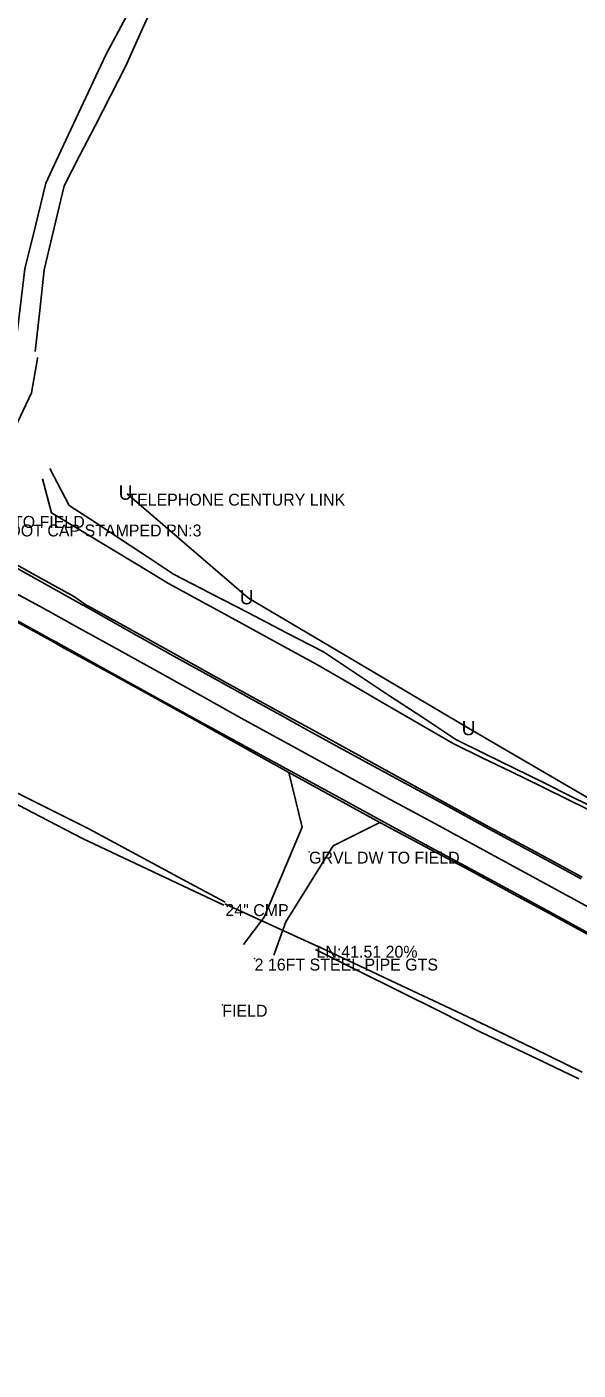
# Model space of a CAD drawing. Extents: x 1411444 to 1458157, y 300965 to 327300.
# Drawn here: x 1455057 to 1455288, y 302301 to 302865 of the extents above; entities that cross this region are included whole.
import ezdxf

# ---------------------------------------------------------------- set-up
doc = ezdxf.new("R2010")
doc.units = 0
for name, color, linetype in [('S_CROSS_DRAIN', 7, 'Continuous'), ('S_CROSS_DRAIN_ANNOT', 7, 'Continuous'), ('S_DITCHLINE', 7, 'Continuous'), ('S_DRG_PT_SYM', 7, 'Continuous'), ('S_DRIVEWAY', 7, 'Continuous'), ('S_EDGE_PAVEMENT', 7, 'Continuous'), ('S_GATE_ANNOT', 7, 'Continuous'), ('S_GRAVEL_ROAD', 7, 'Continuous'), ('S_MSC_PT_SYM', 7, 'Continuous'), ('S_PAVEMENT_CROWN', 7, 'Continuous'), ('S_PRIMARY_CTL_ANNOT', 7, 'Continuous'), ('S_SHOULDER', 7, 'Continuous'), ('S_SURVEY_TEXT_ANNOT', 7, 'Continuous'), ('S_UNDERGROUND_CABLE', 7, 'Continuous'), ('S_UNDERGROUND_CABLE_ANNOT', 7, 'Continuous'), ('S_UTL_PT_SYM', 7, 'Continuous')]:
    doc.layers.add(name, color=color, linetype=linetype)

msp = doc.modelspace()

# ---------------------------------------------------------------- linework, layer by layer
at = {"layer": 'S_CROSS_DRAIN'}
msp.add_line((1455140.29, 302496.55), (1455178.48, 302479.08), dxfattribs=at)
at = {"layer": 'S_DITCHLINE'}
for points in [[(1455066.61, 302679.5), (1455074.81, 302663.92), (1455085.73, 302656.72), (1455096.65, 302649.52), (1455107.57, 302642.32), (1455118.48, 302635.12), (1455134.21, 302626.96), (1455149.93, 302618.8), (1455165.65, 302610.63), (1455181.37, 302602.47), (1455195.25, 302593.27), (1455209.13, 302584.06), (1455223.02, 302574.86), (1455236.9, 302565.66), (1455249.15, 302559.62), (1455261.4, 302553.59), (1455273.64, 302547.56), (1455285.89, 302541.52), (1455298.14, 302535.49)], [(1455063.6, 302675.11), (1455067.32, 302660.8), (1455079.61, 302653.41), (1455091.9, 302646.02), (1455104.19, 302638.62), (1455116.47, 302631.23), (1455132.09, 302622.69), (1455147.7, 302614.14), (1455163.31, 302605.6), (1455178.93, 302597.06), (1455193.14, 302588.8), (1455207.35, 302580.55), (1455221.56, 302572.3), (1455235.77, 302564.05), (1455248.03, 302558.04), (1455260.28, 302552.04), (1455272.54, 302546.03), (1455284.79, 302540.02), (1455297.05, 302534.01)], [(1454871.95, 302633.66), (1454883.03, 302627.47), (1454894.11, 302621.28), (1454905.18, 302615.1), (1454916.26, 302608.91), (1454928.01, 302603.37), (1454939.77, 302597.83), (1454951.52, 302592.28), (1454963.28, 302586.74), (1454975.03, 302581.19), (1454986.79, 302575.65), (1454998.54, 302570.1), (1455010.3, 302564.56), (1455028.48, 302555.45), (1455046.66, 302546.34), (1455064.84, 302537.24), (1455083.02, 302528.13), (1455097.29, 302520.44), (1455111.57, 302512.75), (1455125.84, 302505.06), (1455140.12, 302497.37)], [(1454871.09, 302629.69), (1454893.36, 302618.43), (1454915.62, 302607.16), (1454927.34, 302601.38), (1454939.06, 302595.59), (1454950.79, 302589.81), (1454962.51, 302584.02), (1454974.23, 302578.24), (1454985.95, 302572.46), (1454997.67, 302566.67), (1455009.39, 302560.89), (1455027.12, 302551.71), (1455044.86, 302542.53), (1455062.59, 302533.36), (1455080.32, 302524.18), (1455095.14, 302517.17), (1455109.97, 302510.16), (1455124.79, 302503.15), (1455139.61, 302496.15)], [(1455178.05, 302477.47), (1455195.46, 302468.79), (1455212.88, 302460.11), (1455230.29, 302451.43), (1455247.71, 302442.74), (1455268.1, 302432.98), (1455288.49, 302423.21)], [(1455178.67, 302479.06), (1455196.5, 302470.68), (1455214.33, 302462.29), (1455232.17, 302453.91), (1455250, 302445.52), (1455269.97, 302435.76), (1455289.93, 302426)]]:
    msp.add_lwpolyline(points, dxfattribs=at)
at = {"layer": 'S_DRG_PT_SYM'}
for points in [[(1455140.29, 302496.55), (1455140.29, 302496.6), (1455140.29, 302496.55), (1455140.24, 302496.55), (1455140.29, 302496.55), (1455140.29, 302496.5), (1455140.29, 302496.55), (1455140.34, 302496.55)], [(1455178.48, 302479.08), (1455178.48, 302479.13), (1455178.48, 302479.08), (1455178.43, 302479.08), (1455178.48, 302479.08), (1455178.48, 302479.03), (1455178.48, 302479.08), (1455178.53, 302479.08)]]:
    msp.add_lwpolyline(points, dxfattribs=at)
at = {"layer": 'S_DRIVEWAY'}
for points in [[(1455061.57, 302725.99), (1455061.5, 302725.58), (1455059.01, 302711.26), (1455048.51, 302688.93), (1455038.77, 302670.56), (1455033.52, 302661.31), (1455034.27, 302650.9)], [(1455172.45, 302528.87), (1455166.92, 302551.75)], [(1455147.89, 302479.56), (1455156.52, 302491.02), (1455164.48, 302509.95), (1455172.45, 302528.87)], [(1455185.42, 302521.01), (1455205.08, 302530.8)], [(1455185.42, 302521.01), (1455175.53, 302505.08), (1455165.63, 302489.15), (1455160.59, 302475.08)]]:
    msp.add_lwpolyline(points, dxfattribs=at)
at = {"layer": 'S_EDGE_PAVEMENT'}
for points in [[(1454934.83, 302701.99), (1454950.72, 302693.28), (1454966.61, 302684.56), (1454979.27, 302677.76), (1454991.93, 302670.96), (1455010.69, 302660.75), (1455022.05, 302654.61), (1455032.26, 302648.98), (1455044.91, 302641.94), (1455057.55, 302634.91), (1455076.23, 302624.51), (1455080.5, 302622.13)], [(1454925.81, 302685.46), (1454941.53, 302677.1), (1454957.26, 302668.74), (1454970.34, 302661.62), (1454983.42, 302654.5), (1454998.88, 302645.92), (1455014.34, 302637.35), (1455031.19, 302627.81), (1455048.04, 302618.28), (1455067.2, 302607.72), (1455069.22, 302606.61)], [(1455080.5, 302622.13), (1455080.89, 302621.93)], [(1455080.89, 302621.93), (1455099.64, 302611.35), (1455118.4, 302600.78), (1455134.92, 302591.64), (1455151.45, 302582.5), (1455163.24, 302575.98), (1455175.03, 302569.45), (1455194.4, 302558.88), (1455213.77, 302548.32), (1455232.12, 302538.33), (1455250.46, 302528.34), (1455269.97, 302517.78), (1455289.49, 302507.22)], [(1455069.22, 302606.61), (1455071.42, 302605.36)], [(1455071.42, 302605.36), (1455091.3, 302594.35), (1455111.17, 302583.34), (1455126.49, 302574.94), (1455141.8, 302566.54), (1455154.62, 302559.51), (1455167.43, 302552.49), (1455186.42, 302542.15), (1455205.4, 302531.81), (1455224.11, 302521.65), (1455242.81, 302511.49), (1455261.34, 302501.4), (1455279.86, 302491.31), (1455299.05, 302480.83)]]:
    msp.add_lwpolyline(points, dxfattribs=at)
at = {"layer": 'S_GRAVEL_ROAD'}
for points in [[(1455052.17, 302730.63), (1455054.14, 302746.92), (1455056.11, 302763.21), (1455060.56, 302781.24), (1455065.01, 302799.27), (1455071.31, 302812.73), (1455077.6, 302826.18), (1455083.9, 302839.64), (1455090.19, 302853.09), (1455097.56, 302866.95), (1455104.93, 302880.82)], [(1455060.51, 302728.6), (1455062.4, 302745.72), (1455064.29, 302762.85), (1455068.45, 302780.48), (1455072.61, 302798.11), (1455079.1, 302810.71), (1455085.59, 302823.31), (1455092.08, 302835.91), (1455098.57, 302848.52), (1455105.1, 302863.14), (1455111.62, 302877.76)]]:
    msp.add_lwpolyline(points, dxfattribs=at)
at = {"layer": 'S_MSC_PT_SYM'}
for points in [[(1455175.38, 302518.58), (1455175.38, 302518.63), (1455175.38, 302518.58), (1455175.33, 302518.58), (1455175.38, 302518.58), (1455175.38, 302518.53), (1455175.38, 302518.58), (1455175.43, 302518.58)], [(1455152.54, 302473.69), (1455152.54, 302473.74), (1455152.54, 302473.69), (1455152.49, 302473.69), (1455152.54, 302473.69), (1455152.54, 302473.64), (1455152.54, 302473.69), (1455152.59, 302473.69)], [(1455138.99, 302454.3), (1455138.99, 302454.35), (1455138.99, 302454.3), (1455138.94, 302454.3), (1455138.99, 302454.3), (1455138.99, 302454.25), (1455138.99, 302454.3), (1455139.04, 302454.3)]]:
    msp.add_lwpolyline(points, dxfattribs=at)
at = {"layer": 'S_PAVEMENT_CROWN'}
for points in [[(1454930.49, 302693.61), (1454946.08, 302685.09), (1454961.67, 302676.58), (1454974.63, 302669.63), (1454987.59, 302662.69), (1455002.83, 302654.29), (1455018.06, 302645.89), (1455035.14, 302636.47), (1455052.22, 302627.05), (1455065.61, 302619.76)], [(1455065.61, 302619.76), (1455076.16, 302613.91)], [(1455076.16, 302613.91), (1455095.65, 302603.18), (1455115.15, 302592.45), (1455131.01, 302583.55), (1455146.88, 302574.65), (1455158.92, 302568.06), (1455170.96, 302561.48), (1455190.16, 302551.01), (1455209.36, 302540.54), (1455228.12, 302530.39), (1455246.87, 302520.25), (1455265.89, 302509.87), (1455284.91, 302499.49), (1455303.9, 302489.15)]]:
    msp.add_lwpolyline(points, dxfattribs=at)
at = {"layer": 'S_SHOULDER'}
for points in [[(1454935.57, 302703.19), (1454951.58, 302693.96), (1454967.59, 302684.74), (1454979.96, 302678.32), (1454992.32, 302671.89), (1455011.47, 302662.5), (1455022.58, 302656.19), (1455032.9, 302650.08), (1455045.6, 302642.98), (1455058.3, 302635.88), (1455076.92, 302625.54), (1455077.59, 302625.17)], [(1454925.29, 302684.5), (1454940.65, 302675.41), (1454956.01, 302666.32), (1454967.74, 302659.95), (1454979.48, 302653.58), (1454982.92, 302653.42), (1454998.43, 302645.04), (1455013.94, 302636.66), (1455030.95, 302627.2), (1455047.95, 302617.74), (1455067.03, 302607.19), (1455068.95, 302606.13)], [(1455077.59, 302625.17), (1455081.27, 302622.51)], [(1455081.27, 302622.51), (1455100.07, 302612.07), (1455118.87, 302601.64), (1455135.41, 302592.46), (1455151.96, 302583.29), (1455163.73, 302576.86), (1455175.51, 302570.44), (1455194.85, 302559.79), (1455214.18, 302549.14), (1455232.47, 302539.07), (1455250.76, 302528.99), (1455270.32, 302518.45), (1455289.88, 302507.91)], [(1455071.15, 302604.81), (1455068.95, 302606.13)], [(1455071.15, 302604.81), (1455091.09, 302593.91), (1455111.02, 302583.01), (1455126.28, 302574.49), (1455141.54, 302565.97), (1455154.23, 302558.86), (1455166.92, 302551.75)], [(1455166.92, 302551.75), (1455205.08, 302530.8)], [(1455205.08, 302530.8), (1455223.9, 302520.82), (1455242.71, 302510.84), (1455261.16, 302500.79), (1455279.61, 302490.74), (1455298.71, 302480.31), (1455317.81, 302469.89), (1455333.22, 302461.35), (1455348.62, 302452.82), (1455365.59, 302443.57), (1455382.57, 302434.33), (1455402.96, 302423.1), (1455421.74, 302412.88), (1455440.52, 302402.66), (1455459.74, 302391.98), (1455478.96, 302381.3), (1455497.56, 302371.06), (1455516.17, 302360.82), (1455534.7, 302350.69), (1455553.24, 302340.56), (1455571.49, 302330.6), (1455589.75, 302320.65), (1455607.7, 302310.79), (1455625.65, 302300.93)]]:
    msp.add_lwpolyline(points, dxfattribs=at)
at = {"layer": 'S_UNDERGROUND_CABLE'}
for p, q in [((1455099.13, 302668.86), (1455149.93, 302624.96)), ((1455149.93, 302624.96), (1455242.98, 302570)), ((1455242.98, 302570), (1455343.01, 302511.53))]:
    msp.add_line(p, q, dxfattribs=at)

# ---------------------------------------------------------------- texts
at = {"layer": 'S_CROSS_DRAIN_ANNOT'}
for s, p in [('24" CMP', (1455140.29, 302491.55)), ('LN:41.51 20%', (1455178.48, 302474.08))]:
    msp.add_text(s, height=5, dxfattribs=at).set_placement(p)
at = {"layer": 'S_GATE_ANNOT'}
msp.add_text('2 16FT STEEL PIPE GTS', height=5, dxfattribs=at).set_placement((1455152.54, 302468.69))
at = {"layer": 'S_PRIMARY_CTL_ANNOT'}
msp.add_text('PD:STD ARDOT CAP STAMPED PN:3', height=5, dxfattribs=at).set_placement((1455013.96, 302650.92))
at = {"layer": 'S_SURVEY_TEXT_ANNOT'}
for s, p in [('GR DW TO FIELD', (1455026.3, 302654.52)), ('GRVL DW TO FIELD', (1455175.38, 302513.58)), ('FIELD', (1455138.99, 302449.3))]:
    msp.add_text(s, height=5, dxfattribs=at).set_placement(p)
at = {"layer": 'S_UNDERGROUND_CABLE_ANNOT'}
msp.add_text('TELEPHONE CENTURY LINK', height=5, dxfattribs=at).set_placement((1455099.13, 302663.86))
at = {"layer": 'S_UTL_PT_SYM'}
for p in [(1455095.5, 302666.31), (1455146.3, 302622.41), (1455239.35, 302567.45)]:
    msp.add_text('U', height=6, rotation=360, dxfattribs=at).set_placement(p)

doc.saveas('drawing.dxf')
